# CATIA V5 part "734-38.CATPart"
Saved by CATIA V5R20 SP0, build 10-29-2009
Part number: 734-38
Bounding box of the stored display mesh (mm): x -33 to 33, y -32.999 to 32.999, z -47 to 63
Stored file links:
  C:\Users\Utente\Desktop\IO LAVORO\3D X SITO CF\X SITO\734\734-38.CATPart
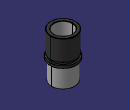
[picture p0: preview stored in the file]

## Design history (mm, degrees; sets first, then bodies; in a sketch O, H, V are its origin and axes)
Set1
  DatumSurface1 to DatumSurface25 "734-38"
Body1 (main body)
